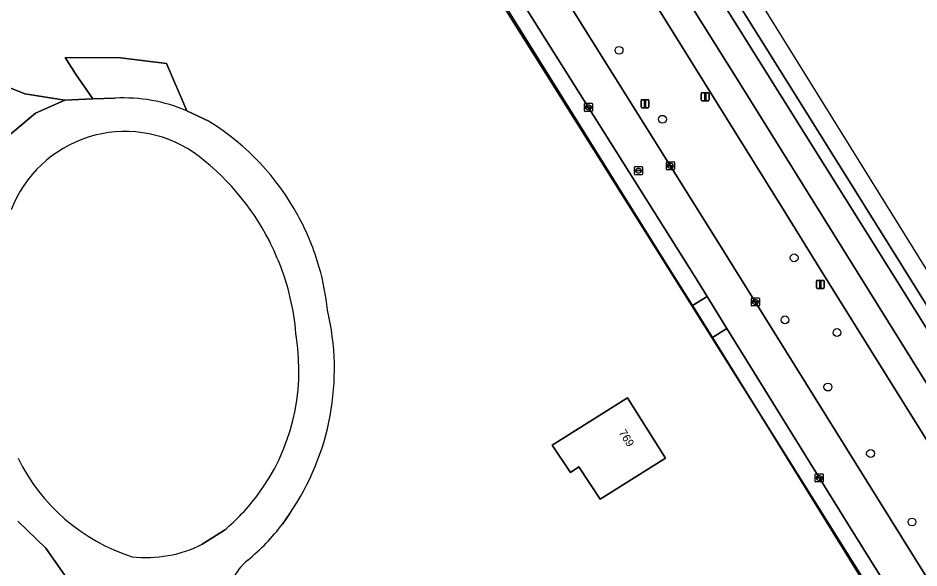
# Model space of a CAD drawing. Extents: x 158132 to 159664, y 385256 to 387218.
# Drawn here: x 159168.9 to 159281.4, y 386462.5 to 386531.1 of the extents above; entities that cross this region are included whole.
import ezdxf

# ---------------------------------------------------------------- set-up
doc = ezdxf.new("R2010")
doc.units = 0
for name, color, linetype in [('IMGEO_Berm_groen', 7, 'Continuous'), ('IMGEO_Berm_open', 7, 'Continuous'), ('IMGEO_Boom', 7, 'Continuous'), ('IMGEO_Grasland_overig', 7, 'Continuous'), ('IMGEO_Groenvoorziening', 7, 'Continuous'), ('IMGEO_Hek', 7, 'Continuous'), ('IMGEO_Kolk', 7, 'Continuous'), ('IMGEO_Lichtmast', 7, 'Continuous'), ('IMGEO_Loofbos', 7, 'Continuous'), ('IMGEO_Pand', 7, 'Continuous'), ('IMGEO_Pand_nummerreeks', 7, 'Continuous'), ('IMGEO_Rijbaan_lokaal_gesloten', 7, 'Continuous'), ('IMGEO_Rijbaan_lokaal_open', 7, 'Continuous'), ('IMGEO_Rijbaan_regionaal_gesloten', 7, 'Continuous'), ('IMGEO_Rioolput', 7, 'Continuous'), ('IMGEO_Verkeersbordpaal', 7, 'Continuous'), ('IMGEO_Voetpad_open', 7, 'Continuous')]:
    doc.layers.add(name, color=color, linetype=linetype)

msp = doc.modelspace()

# ---------------------------------------------------------------- linework, layer by layer
at = {"layer": 'IMGEO_Berm_groen'}
for points in [[(159450.9, 386207.96), (159427.26, 386246.56), (159425.1, 386250), (159405.9, 386280.49), (159387.21, 386310.53), (159345.73, 386377.33), (159334.62, 386395.01), (159326.35, 386408.09), (159320.18, 386417.89), (159312.88, 386429.61), (159302.23, 386446.71), (159294.43, 386459.19), (159268.99, 386500), (159264.8, 386506.73), (159232.99, 386557.93)], [(159237.38, 386533.49), (159256.22, 386503.4), (159258.34, 386500), (159274.93, 386473.31), (159298.35, 386435.69), (159305.08, 386424.92), (159316.19, 386407.15), (159337.12, 386373.76), (159339.93, 386369.27), (159350.12, 386352.97), (159352.77, 386348.74), (159360.58, 386336.26), (159392.53, 386284.71), (159414.26, 386250), (159436.59, 386214.4)]]:
    msp.add_lwpolyline(points, dxfattribs=at)
at = {"layer": 'IMGEO_Berm_open'}
msp.add_lwpolyline([(159326.37, 386424.73), (159294.97, 386475.13), (159279.46, 386500), (159265.17, 386522.91), (159244.66, 386555.67), (159234.98, 386571.21), (159233.96, 386572.84), (159232.64, 386572.02), (159233.68, 386570.42), (159242.94, 386555.56), (159253.77, 386538.11), (159277.62, 386500), (159288.12, 386483.23), (159318.51, 386434.33), (159340.68, 386398.8), (159342.02, 386399.64)], close=True, dxfattribs=at)
at = {"layer": 'IMGEO_Boom'}
for centre in [(159243.99, 386527.11), (159249.41, 386518.5), (159265.85, 386501.2), (159264.71, 386493.45), (159271.21, 386491.87), (159270.07, 386485.06), (159275.4, 386476.77), (159280.58, 386468.21)]:
    msp.add_circle(centre, 0.489, dxfattribs=at)
at = {"layer": 'IMGEO_Grasland_overig'}
msp.add_lwpolyline([(159190.01, 386519.54), (159187.45, 386525.47), (159181.71, 386526.16), (159174.8, 386526.21), (159176.12, 386524.17), (159178.27, 386521.04), (159181.05, 386521.12)], dxfattribs=at)
msp.add_arc((159182.13, 386501.04), 20.12, 66.9352, 93.0802, dxfattribs=at)
at = {"layer": 'IMGEO_Groenvoorziening'}
for points in [[(159174.8, 386461.48), (159172.42, 386464.95), (159168.9, 386468.32)], [(159191.92, 386465.44), (159194.7, 386467.19)]]:
    msp.add_lwpolyline(points, dxfattribs=at)
for centre, radius, start, end in [((159182.32, 386501.67), 15.3, 56.3026, 158.8201), ((159172.41, 386489.02), 31.35, 27.1055, 54.0571), ((159172.57, 386489.09), 31.17, 20.476, 27.1205), ((159172.41, 386489.03), 31.35, 3.9543, 20.4927), ((159178.07, 386487.1), 25.94, 323.2063, 9.0718), ((159190.44, 386486.69), 23.94, 206.0142, 252.3223), ((159178.07, 386487.09), 25.93, 309.8934, 323.2182), ((159184.96, 386479.18), 15.4, 263.3265, 296.8575)]:
    msp.add_arc(centre, radius, start, end, dxfattribs=at)
at = {"layer": 'IMGEO_Hek'}
for points in [[(159250.06, 386500), (159194.34, 386588.63), (159192.21, 386592.03)], [(159278.19, 386454.83), (159261.26, 386482.17), (159250.06, 386500)]]:
    msp.add_lwpolyline(points, dxfattribs=at)
at = {"layer": 'IMGEO_Kolk'}
for p, q in [((159239.66, 386519.56), (159239.66, 386520.41)), ((159239.74, 386520.49), (159240.59, 386520.49)), ((159240.15, 386520.26), (159240.18, 386520.26)), ((159240.67, 386520.41), (159240.67, 386519.56)), ((159240.59, 386519.48), (159239.74, 386519.48)), ((159239.92, 386519.98), (159239.92, 386519.99)), ((159240.36, 386519.94), (159239.96, 386519.94)), ((159239.97, 386520.03), (159240.36, 386520.03)), ((159240.17, 386519.71), (159240.15, 386519.71)), ((159240.41, 386519.99), (159240.41, 386519.98)), ((159249.9, 386512.27), (159249.9, 386513.12)), ((159249.98, 386513.19), (159250.83, 386513.19)), ((159250.83, 386512.19), (159249.98, 386512.19)), ((159250.16, 386512.69), (159250.16, 386512.7)), ((159250.2, 386512.74), (159250.6, 386512.74)), ((159250.6, 386512.65), (159250.2, 386512.65)), ((159250.39, 386512.97), (159250.41, 386512.97)), ((159250.41, 386512.41), (159250.39, 386512.41)), ((159250.64, 386512.7), (159250.64, 386512.69)), ((159250.9, 386513.12), (159250.9, 386512.27)), ((159260.52, 386495.26), (159260.52, 386496.12)), ((159260.59, 386496.19), (159261.44, 386496.19)), ((159260.77, 386495.68), (159260.77, 386495.7)), ((159261.21, 386495.65), (159260.81, 386495.65)), ((159260.82, 386495.73), (159261.22, 386495.73)), ((159261, 386495.97), (159261.03, 386495.97)), ((159261.03, 386495.41), (159261, 386495.41)), ((159261.26, 386495.7), (159261.26, 386495.68)), ((159261.52, 386496.12), (159261.52, 386495.26)), ((159261.44, 386495.19), (159260.59, 386495.19)), ((159268.49, 386473.29), (159268.49, 386474.14)), ((159268.57, 386474.22), (159269.42, 386474.22)), ((159268.98, 386473.99), (159269, 386473.99)), ((159269.49, 386474.14), (159269.49, 386473.29)), ((159269.42, 386473.21), (159268.57, 386473.21)), ((159268.75, 386473.71), (159268.75, 386473.72)), ((159268.79, 386473.76), (159269.19, 386473.76)), ((159269.19, 386473.67), (159268.79, 386473.67)), ((159269, 386473.44), (159268.98, 386473.44)), ((159269.23, 386473.72), (159269.23, 386473.71))]:
    msp.add_line(p, q, dxfattribs=at)
for points in [[(159239.66, 386519.56), (159239.66, 386520.41)], [(159239.74, 386520.49), (159240.59, 386520.49)], [(159240.67, 386520.41), (159240.67, 386519.56)], [(159240.59, 386519.48), (159239.74, 386519.48)], [(159249.9, 386512.27), (159249.9, 386513.12)], [(159249.98, 386513.19), (159250.83, 386513.19)], [(159250.83, 386512.19), (159249.98, 386512.19)], [(159250.9, 386513.12), (159250.9, 386512.27)], [(159260.52, 386495.26), (159260.52, 386496.12)], [(159260.59, 386496.19), (159261.44, 386496.19)], [(159261.52, 386496.12), (159261.52, 386495.26)], [(159261.44, 386495.19), (159260.59, 386495.19)], [(159268.49, 386473.29), (159268.49, 386474.14)], [(159268.57, 386474.22), (159269.42, 386474.22)], [(159269.49, 386474.14), (159269.49, 386473.29)], [(159269.42, 386473.21), (159268.57, 386473.21)]]:
    msp.add_lwpolyline(points, dxfattribs=at)
for centre, radius, start, end in [((159239.74, 386520.41), 0.0765, 91.552, 178.448), ((159239.74, 386520.41), 0.0765, 91.552, 178.448), ((159240.59, 386520.41), 0.0765, 1.552, 88.448), ((159240.59, 386520.41), 0.0765, 1.552, 88.448), ((159239.74, 386519.56), 0.0765, 181.552, 268.448), ((159239.74, 386519.56), 0.0765, 181.552, 268.448), ((159239.96, 386519.99), 0.0403, 85.8775, 175.7526), ((159239.96, 386519.98), 0.0366, 178.938, 274.7102), ((159240.37, 386519.99), 0.0386, 1.7309, 96.639), ((159240.36, 386519.98), 0.043, 264.8664, 352.4533), ((159240.59, 386519.56), 0.0765, 271.552, 358.448), ((159240.59, 386519.56), 0.0765, 271.552, 358.448), ((159249.98, 386513.12), 0.0765, 91.552, 178.448), ((159249.98, 386513.12), 0.0765, 91.552, 178.448), ((159249.98, 386512.27), 0.0765, 181.552, 268.448), ((159249.98, 386512.27), 0.0765, 181.552, 268.448), ((159250.2, 386512.7), 0.0403, 85.8775, 175.7526), ((159250.2, 386512.69), 0.0366, 178.938, 274.7102), ((159250.61, 386512.7), 0.0386, 1.7309, 96.639), ((159250.6, 386512.69), 0.043, 264.8664, 352.4533), ((159250.83, 386513.12), 0.0765, 1.552, 88.448), ((159250.83, 386513.12), 0.0765, 1.552, 88.448), ((159250.83, 386512.27), 0.0765, 271.552, 358.448), ((159250.83, 386512.27), 0.0765, 271.552, 358.448), ((159260.59, 386496.11), 0.0765, 91.552, 178.448), ((159260.59, 386496.11), 0.0765, 91.552, 178.448), ((159260.82, 386495.69), 0.0403, 85.8775, 175.7526), ((159260.81, 386495.68), 0.0366, 178.938, 274.7102), ((159261.22, 386495.69), 0.043, 264.8664, 352.4533), ((159261.22, 386495.69), 0.0386, 1.7309, 96.639), ((159261.44, 386496.11), 0.0765, 1.552, 88.448), ((159261.44, 386496.11), 0.0765, 1.552, 88.448), ((159260.59, 386495.26), 0.0765, 181.552, 268.448), ((159260.59, 386495.26), 0.0765, 181.552, 268.448), ((159261.44, 386495.26), 0.0765, 271.552, 358.448), ((159261.44, 386495.26), 0.0765, 271.552, 358.448), ((159268.57, 386474.14), 0.0765, 91.552, 178.448), ((159268.57, 386474.14), 0.0765, 91.552, 178.448), ((159269.42, 386474.14), 0.0765, 1.552, 88.448), ((159269.42, 386474.14), 0.0765, 1.552, 88.448), ((159268.57, 386473.29), 0.0765, 181.552, 268.448), ((159268.57, 386473.29), 0.0765, 181.552, 268.448), ((159268.79, 386473.72), 0.0403, 85.8775, 175.7526), ((159268.79, 386473.71), 0.0366, 178.938, 274.7102), ((159269.2, 386473.72), 0.0386, 1.7309, 96.639), ((159269.19, 386473.71), 0.043, 264.8664, 352.4533), ((159269.42, 386473.29), 0.0765, 271.552, 358.448), ((159269.42, 386473.29), 0.0765, 271.552, 358.448)]:
    msp.add_arc(centre, radius, start, end, dxfattribs=at)
for centre, major_axis, ratio, start_param, end_param in [((159240.15, 386519.98), (-0.387, 0.002), 0.722429, 4.712389, 7.853982), ((159240.18, 386519.98), (-0.39, 0.002), 0.717154, 1.570796, 4.712389), ((159250.39, 386512.69), (-0.387, 0.002), 0.722429, 4.712389, 7.853982), ((159250.41, 386512.69), (-0.39, 0.002), 0.717154, 1.570796, 4.712389), ((159261, 386495.69), (-0.387, 0.002), 0.722429, 4.712389, 7.853982), ((159261.03, 386495.69), (-0.39, 0.002), 0.717154, 1.570796, 4.712389), ((159268.98, 386473.71), (-0.387, 0.002), 0.722429, 4.712389, 7.853982), ((159269, 386473.71), (-0.39, 0.002), 0.717154, 1.570796, 4.712389)]:
    msp.add_ellipse(centre, major_axis=major_axis, ratio=ratio, start_param=start_param, end_param=end_param, dxfattribs=at)
at = {"layer": 'IMGEO_Lichtmast'}
for p, q in [((159254.26, 386520.91), (159254.26, 386521.71)), ((159254.26, 386521.71), (159254.26, 386520.91)), ((159254.36, 386521.81), (159255.15, 386521.81)), ((159255.15, 386521.81), (159254.36, 386521.81)), ((159255.25, 386521.71), (159255.25, 386520.91)), ((159255.25, 386520.91), (159255.25, 386521.71)), ((159255.15, 386520.81), (159254.36, 386520.81)), ((159254.36, 386520.81), (159255.15, 386520.81)), ((159268.63, 386497.48), (159268.63, 386498.28)), ((159268.63, 386498.28), (159268.63, 386497.48)), ((159268.73, 386498.38), (159269.52, 386498.38)), ((159269.52, 386498.38), (159268.73, 386498.38)), ((159269.62, 386498.28), (159269.62, 386497.48)), ((159269.62, 386497.48), (159269.62, 386498.28)), ((159269.52, 386497.38), (159268.73, 386497.38)), ((159268.73, 386497.38), (159269.52, 386497.38))]:
    msp.add_line(p, q, dxfattribs=at)
for points in [[(159254.68, 386521.68), (159254.83, 386521.68), (159254.83, 386520.93), (159254.68, 386520.93), (159254.68, 386521.68)], [(159269.05, 386498.26), (159269.2, 386498.26), (159269.2, 386497.51), (159269.05, 386497.51), (159269.05, 386498.26)]]:
    msp.add_lwpolyline(points, dxfattribs=at)
for centre, start, end in [((159254.36, 386521.71), 90, 180), ((159254.36, 386521.71), 90, 180), ((159255.15, 386521.71), 0, 90), ((159255.15, 386521.71), 360, 90), ((159254.36, 386520.91), 180, 270), ((159254.36, 386520.91), 180, 270), ((159255.15, 386520.91), 270, 0), ((159255.15, 386520.91), 270, 0), ((159268.73, 386498.28), 90, 180), ((159268.73, 386498.28), 90, 180), ((159269.52, 386498.28), 0, 90), ((159269.52, 386498.28), 360, 90), ((159268.73, 386497.48), 180, 270), ((159268.73, 386497.48), 180, 270), ((159269.52, 386497.48), 270, 0), ((159269.52, 386497.48), 270, 0)]:
    msp.add_arc(centre, 0.1, start, end, dxfattribs=at)
at = {"layer": 'IMGEO_Loofbos'}
for points in [[(159500, 386100.31), (159430.86, 386210.85), (159406.37, 386250), (159377.74, 386296.22), (159335.56, 386363.38), (159320.93, 386386.67), (159299.26, 386421.42), (159282.86, 386447.72), (159281.62, 386449.7), (159261.29, 386482.19), (159255.64, 386491.24), (159253.15, 386495.23), (159250.17, 386500), (159194.12, 386589.79)], [(159158.23, 386537.96), (159157.57, 386530.99), (159159.49, 386527.35), (159160.75, 386526.52), (159162.89, 386525.18), (159166.8, 386522.9), (159169.77, 386521.66), (159174.79, 386520.88), (159178.27, 386521.04), (159176.12, 386524.17), (159174.8, 386526.21), (159181.71, 386526.16), (159187.45, 386525.47), (159190.01, 386519.54), (159192.83, 386518.2)], [(159202.88, 386469.27), (159201.96, 386467.95)]]:
    msp.add_lwpolyline(points, dxfattribs=at)
msp.add_lwpolyline([(159237.93, 386474.4), (159235.65, 386477.8), (159245.05, 386483.72), (159249.78, 386476.2), (159241.64, 386471.08), (159238.95, 386475.09)], close=True, dxfattribs=at)
for centre, radius, start, end in [((159176.12, 386491.33), 31.64, 28.4871, 58.1064), ((159176.14, 386491.34), 31.62, 15.8888, 28.4926), ((159175.99, 386491.32), 31.77, 6.0783, 15.8613), ((159176.49, 386487.29), 31.95, 325.6699, 13.3646), ((159180.84, 386484.02), 26.54, 309.2185, 322.7284), ((159202.49, 386457.69), 7.56, 130.1649, 154.13)]:
    msp.add_arc(centre, radius, start, end, dxfattribs=at)
at = {"layer": 'IMGEO_Pand'}
msp.add_lwpolyline([(159241.64, 386471.08), (159249.78, 386476.2), (159245.05, 386483.72), (159235.65, 386477.8), (159237.93, 386474.4), (159238.95, 386475.09)], close=True, dxfattribs=at)
at = {"layer": 'IMGEO_Rijbaan_lokaal_gesloten'}
for points in [[(159167.43, 386516.2), (159171.12, 386519.25), (159174.79, 386520.88), (159169.77, 386521.66), (159166.8, 386522.9)], [(159181.05, 386521.12), (159178.27, 386521.04), (159174.79, 386520.88), (159171.12, 386519.25), (159167.43, 386516.2), (159164.32, 386511.52), (159163.38, 386507.51), (159161.8, 386501.6), (159161.54, 386500), (159161.2, 386497.88), (159159.92, 386496.01), (159158.48, 386495.81), (159159.22, 386490.06)], [(159192.83, 386518.2), (159190.01, 386519.54)], [(159168.9, 386468.32), (159172.42, 386464.95), (159174.8, 386461.48), (159179.96, 386459.17), (159185.54, 386458.14), (159186.96, 386458.39)], [(159201.96, 386467.95), (159202.88, 386469.27)], [(159194.7, 386467.19), (159191.92, 386465.44)]]:
    msp.add_lwpolyline(points, dxfattribs=at)
for centre, radius, start, end in [((159182.13, 386501.04), 20.12, 66.9352, 93.0802), ((159176.12, 386491.33), 31.64, 28.4871, 58.1064), ((159182.32, 386501.67), 15.3, 56.3026, 158.8201), ((159172.41, 386489.02), 31.35, 27.1055, 54.0571), ((159176.14, 386491.34), 31.62, 15.8888, 28.4926), ((159172.57, 386489.09), 31.17, 20.476, 27.1205), ((159172.41, 386489.03), 31.35, 3.9543, 20.4927), ((159175.99, 386491.32), 31.77, 6.0783, 15.8613), ((159176.49, 386487.29), 31.95, 325.6699, 13.3646), ((159178.07, 386487.1), 25.94, 323.2063, 9.0718), ((159190.44, 386486.69), 23.94, 206.0142, 252.3223), ((159178.07, 386487.09), 25.93, 309.8934, 323.2182), ((159180.84, 386484.02), 26.54, 309.2185, 322.7284), ((159184.96, 386479.18), 15.4, 263.3265, 296.8575), ((159202.49, 386457.69), 7.56, 130.1649, 154.13)]:
    msp.add_arc(centre, radius, start, end, dxfattribs=at)
at = {"layer": 'IMGEO_Rijbaan_lokaal_open'}
for points in [[(159231.68, 386533.49), (159252.73, 386500), (159253.77, 386498.34), (159255, 386496.36), (159257.46, 386492.38), (159272.54, 386467.97), (159295.37, 386431.39), (159300.96, 386422.44), (159318.51, 386394.36), (159336.87, 386365.14), (159342.27, 386356.54), (159368.42, 386314.26), (159377.54, 386299.63), (159408.52, 386250), (159416.04, 386237.98), (159432.37, 386211.79), (159444.43, 386192.43)], [(159392.53, 386284.71), (159360.58, 386336.26), (159352.77, 386348.74), (159350.12, 386352.97), (159339.93, 386369.27), (159337.12, 386373.76), (159316.19, 386407.15), (159305.08, 386424.92), (159298.35, 386435.69), (159274.93, 386473.31), (159258.34, 386500), (159256.22, 386503.4), (159237.38, 386533.49)]]:
    msp.add_lwpolyline(points, dxfattribs=at)
at = {"layer": 'IMGEO_Rijbaan_regionaal_gesloten'}
for points in [[(159343.88, 386400.8), (159254.18, 386545.24), (159229.66, 386584.59), (159229.66, 386584.59), (159228.15, 386583.68), (159233.96, 386572.84), (159234.98, 386571.21), (159244.66, 386555.67), (159265.17, 386522.91), (159279.46, 386500), (159294.97, 386475.13), (159326.37, 386424.73), (159342.02, 386399.64), (159343.88, 386400.8)], [(159226.04, 386582.21), (159225.95, 386582.35), (159222.99, 386580.57), (159259.04, 386523.03), (159337.59, 386396.88), (159340.68, 386398.8), (159318.51, 386434.33), (159288.12, 386483.23), (159277.62, 386500), (159253.77, 386538.11), (159242.94, 386555.56), (159233.68, 386570.42), (159232.64, 386572.02)], [(159222.99, 386580.57), (159219.83, 386578.66), (159222.73, 386574.37), (159229.11, 386564.24), (159230.94, 386561.23), (159232.99, 386557.93), (159264.8, 386506.73), (159268.99, 386500), (159294.43, 386459.19), (159302.23, 386446.71), (159312.88, 386429.61), (159320.18, 386417.89), (159326.35, 386408.09), (159334.62, 386395.01), (159337.59, 386396.88), (159259.04, 386523.03)]]:
    msp.add_lwpolyline(points, close=True, dxfattribs=at)
at = {"layer": 'IMGEO_Rioolput'}
for p, q in [((159245.91, 386511.66), (159245.91, 386512.51)), ((159245.98, 386512.59), (159246.84, 386512.59)), ((159246.4, 386512.36), (159246.42, 386512.36)), ((159246.91, 386512.51), (159246.91, 386511.66)), ((159246.84, 386511.58), (159245.98, 386511.58)), ((159246.17, 386512.08), (159246.17, 386512.09)), ((159246.21, 386512.13), (159246.61, 386512.13)), ((159246.61, 386512.04), (159246.21, 386512.04)), ((159246.42, 386511.81), (159246.4, 386511.81)), ((159246.65, 386512.09), (159246.65, 386512.08))]:
    msp.add_line(p, q, dxfattribs=at)
for points in [[(159245.91, 386511.66), (159245.91, 386512.51)], [(159245.98, 386512.59), (159246.84, 386512.59)], [(159246.91, 386512.51), (159246.91, 386511.66)], [(159246.84, 386511.58), (159245.98, 386511.58)]]:
    msp.add_lwpolyline(points, dxfattribs=at)
for centre, radius, start, end in [((159245.99, 386512.51), 0.0765, 91.552, 178.448), ((159245.99, 386512.51), 0.0765, 91.552, 178.448), ((159246.83, 386512.51), 0.0765, 1.552, 88.448), ((159246.83, 386512.51), 0.0765, 1.552, 88.448), ((159245.99, 386511.66), 0.0765, 181.552, 268.448), ((159245.99, 386511.66), 0.0765, 181.552, 268.448), ((159246.21, 386512.09), 0.0403, 85.8775, 175.7526), ((159246.21, 386512.08), 0.0366, 178.938, 274.7102), ((159246.61, 386512.09), 0.0386, 1.7309, 96.639), ((159246.61, 386512.08), 0.043, 264.8664, 352.4533), ((159246.83, 386511.66), 0.0765, 271.552, 358.448), ((159246.83, 386511.66), 0.0765, 271.552, 358.448)]:
    msp.add_arc(centre, radius, start, end, dxfattribs=at)
for centre, major_axis, ratio, start_param, end_param in [((159246.4, 386512.08), (-0.387, 0.002), 0.722429, 4.712389, 7.853982), ((159246.42, 386512.08), (-0.39, 0.002), 0.717154, 1.570796, 4.712389)]:
    msp.add_ellipse(centre, major_axis=major_axis, ratio=ratio, start_param=start_param, end_param=end_param, dxfattribs=at)
at = {"layer": 'IMGEO_Verkeersbordpaal'}
for p, q in [((159246.73, 386520.04), (159246.73, 386520.84)), ((159246.73, 386520.84), (159246.73, 386520.04)), ((159246.83, 386520.94), (159247.62, 386520.94)), ((159247.62, 386520.94), (159246.83, 386520.94)), ((159247.72, 386520.84), (159247.72, 386520.04)), ((159247.72, 386520.04), (159247.72, 386520.84)), ((159247.62, 386519.94), (159246.83, 386519.94)), ((159246.83, 386519.94), (159247.62, 386519.94))]:
    msp.add_line(p, q, dxfattribs=at)
msp.add_lwpolyline([(159247.15, 386520.81), (159247.3, 386520.81), (159247.3, 386520.06), (159247.15, 386520.06), (159247.15, 386520.81)], dxfattribs=at)
for centre, start, end in [((159246.83, 386520.84), 90, 180), ((159246.83, 386520.84), 90, 180), ((159247.62, 386520.84), 0, 90), ((159247.62, 386520.84), 360, 90), ((159246.83, 386520.04), 180, 270), ((159246.83, 386520.04), 180, 270), ((159247.62, 386520.04), 270, 0), ((159247.62, 386520.04), 270, 0)]:
    msp.add_arc(centre, 0.1, start, end, dxfattribs=at)
at = {"layer": 'IMGEO_Voetpad_open'}
for points in [[(159179.41, 386614.47), (159186.99, 386602.11), (159187.27, 386601.66), (159188.39, 386599.7), (159190.77, 386595.59), (159192.73, 386592.19), (159194.12, 386589.79), (159250.17, 386500), (159253.15, 386495.23), (159255, 386496.36), (159253.77, 386498.34), (159252.73, 386500), (159231.68, 386533.49), (159209.62, 386568.89), (159197.67, 386587.77)], [(159342.27, 386356.54), (159336.87, 386365.14), (159318.51, 386394.36), (159300.96, 386422.44), (159295.37, 386431.39), (159272.54, 386467.97), (159257.46, 386492.38), (159255.64, 386491.24), (159261.29, 386482.19), (159281.62, 386449.7), (159282.86, 386447.72), (159299.26, 386421.42), (159320.93, 386386.67), (159335.56, 386363.38), (159377.74, 386296.22), (159406.37, 386250), (159430.86, 386210.85), (159500, 386100.31), (159562.61, 386000.29), (159562.79, 386000), (159565.37, 385995.91), (159566.44, 385994.98), (159567.43, 385994.12), (159577.44, 385985.43)]]:
    msp.add_lwpolyline(points, dxfattribs=at)
msp.add_lwpolyline([(159253.15, 386495.23), (159255.64, 386491.24), (159257.46, 386492.38), (159255, 386496.36)], close=True, dxfattribs=at)

# ---------------------------------------------------------------- texts
at = {"layer": 'IMGEO_Pand_nummerreeks'}
msp.add_text('769', height=1, rotation=302.1976, dxfattribs=at).set_placement((159243.91, 386479.38))

doc.saveas('drawing.dxf')
